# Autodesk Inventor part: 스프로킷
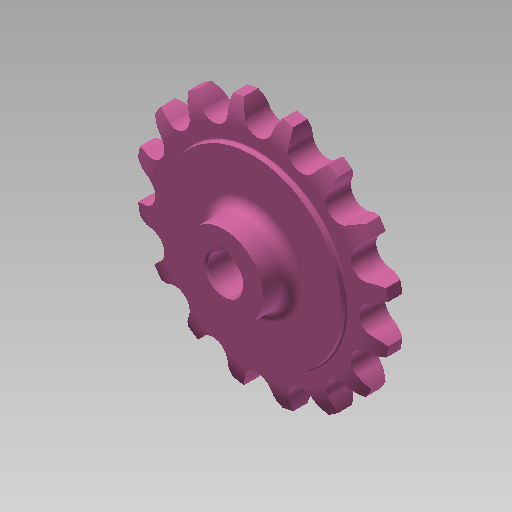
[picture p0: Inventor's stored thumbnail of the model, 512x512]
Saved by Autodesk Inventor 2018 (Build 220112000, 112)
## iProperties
Created: 2016-03
Part Number: 스프로킷
Material: 강철, 탄소
Document SubType Name: Modeling
Designer: mduedu
Density: 7.87 g/cm^3
Mass: 230.696 g
Surface Area: 96.4947 cm^2
Volume: 29.3133 cm^3
Appearance: 분홍색
Author: mduedu
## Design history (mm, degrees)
sketch "스케치1"
  geometry: L1 (0, 5)-(25, 5); L2 (25, 5)-(25, 4.1); L3 (25.5, 3.6)-(29.125, 3.6); L4 (35.5, 2)-(35.5, 0); L5 (35.5, 0)-(0, 0); L6 (0, 0)-(0, 5); L7 (0, -5)-(25, -5); L8 (25, -5)-(25, -4.1); L9 (25.5, -3.6)-(29.125, -3.6); L10 (35.5, -2)-(35.5, 0); L11 (0, 0)-(0, -5); A1 r 13.5 centre (29.125, -9.9) between (35.5, 2) and (29.125, 3.6); A2 r 13.5 centre (29.125, 9.9) between (29.125, -3.6) and (35.5, -2); A3 r 0.5 centre (25.5, 4.1) between (25, 4.1) and (25.5, 3.6); A4 r 0.5 centre (25.5, -4.1) between (25.5, -3.6) and (25, -4.1); 2 further points
  constraints: 22 end point, 8 point on circle, 6 symmetric about line, 5 tangent, 4 centre point, 4 parallel, 4 point on line, 1 equal radius, 1 horizontal, 1 perpendicular, 1 other
  dimensions: "d0" = 71 diameter of L4 L6; "d2" = 50 diameter of L2 L6; "d3" = 1.6 vertical distance of L4.start L3.end; "d4" = 3.6 distance from line of L4.end L3; "d5" = 5 distance between parallel lines of L5 L1; "d6" = 13.5 radius of A1; "d15" = 0.5 radius of A3
revolve "회전1" sketch "스케치1" stored, may be unused: angle "d7" = 90 deg
sketch "스케치2" dims "d8" = 57.16, "d11" = 71
  geometry: L1 (0, 0)-(0, 28.58); A1 r 32.55 centre (0, 0) between (-16.114, 28.281) and (0, 32.55); A2 r 3.97 centre (0, 32.55) between (-3.838, 31.533) and (0, 28.58); A3 r 12.7 centre (-16.114, 28.281) between (-3.838, 31.533) and (-5.392, 35.088); A4 r 12.7 centre (16.114, 28.281) between (5.392, 35.088) and (3.838, 31.533); A5 r 3.97 centre (0, 32.55) between (0, 28.58) and (3.838, 31.533); A6 r 35.5 centre (0, 0) between (5.392, 35.088) and (-5.392, 35.088); 2 further points
  constraints: 12 point on circle, 6 centre point, 4 coincident, 3 symmetric about line, 2 end point, 1 point on line, 1 tangent, 1 vertical, 1 vertical alignment, 7 other
  dimensions: "d10" = 65.1 diameter of A1; "d12" = 12.7 radius of A3
extrude "돌출1" cut sketch "스케치2" extent not by distance; stored distance "d13" = 10; taper "d14" = 0 deg
sketch "스케치3"
  geometry: C1 r 11 at (0, 0); 1 further point
  constraints: 1 centre point, 1 coincident
  dimensions: "d19" = 22 diameter of C1
extrude "돌출2" join sketch "스케치3" distance "d20" = 8; taper "d21" = 0 deg
fillet "모깎기1" dims "d22" = 3
sketch "스케치4"
  geometry: L1 (-1.5, 0)-(1.5, 0); L2 (1.5, 0)-(1.5, 6.4); L3 (1.5, 6.4)-(-1.5, 6.4); L4 (-1.5, 6.4)-(-1.5, 0); C1 r 5 at (0, 0); 2 further points
  constraints: 8 end point, 2 coincident, 2 parallel, 1 centre point, 1 horizontal, 1 midpoint, 1 perpendicular
  dimensions: "d23" = 10 diameter of C1; "d25" = 3 distance of L2.end L3.end; "d26" = 6.4 distance of L1.end L2.end
extrude "돌출3" cut sketch "스케치4" extent not by distance; stored distance "d27" = 8; taper "d28" = 0 deg
chamfer "모따기1" distance "d29" = 0.5; stored, may be unused: second distance "d30" = 2, angle "d31" = 45 deg
node "솔리드1"
pattern_circular "원형 패턴1" dims angle "d17" = 360 deg
